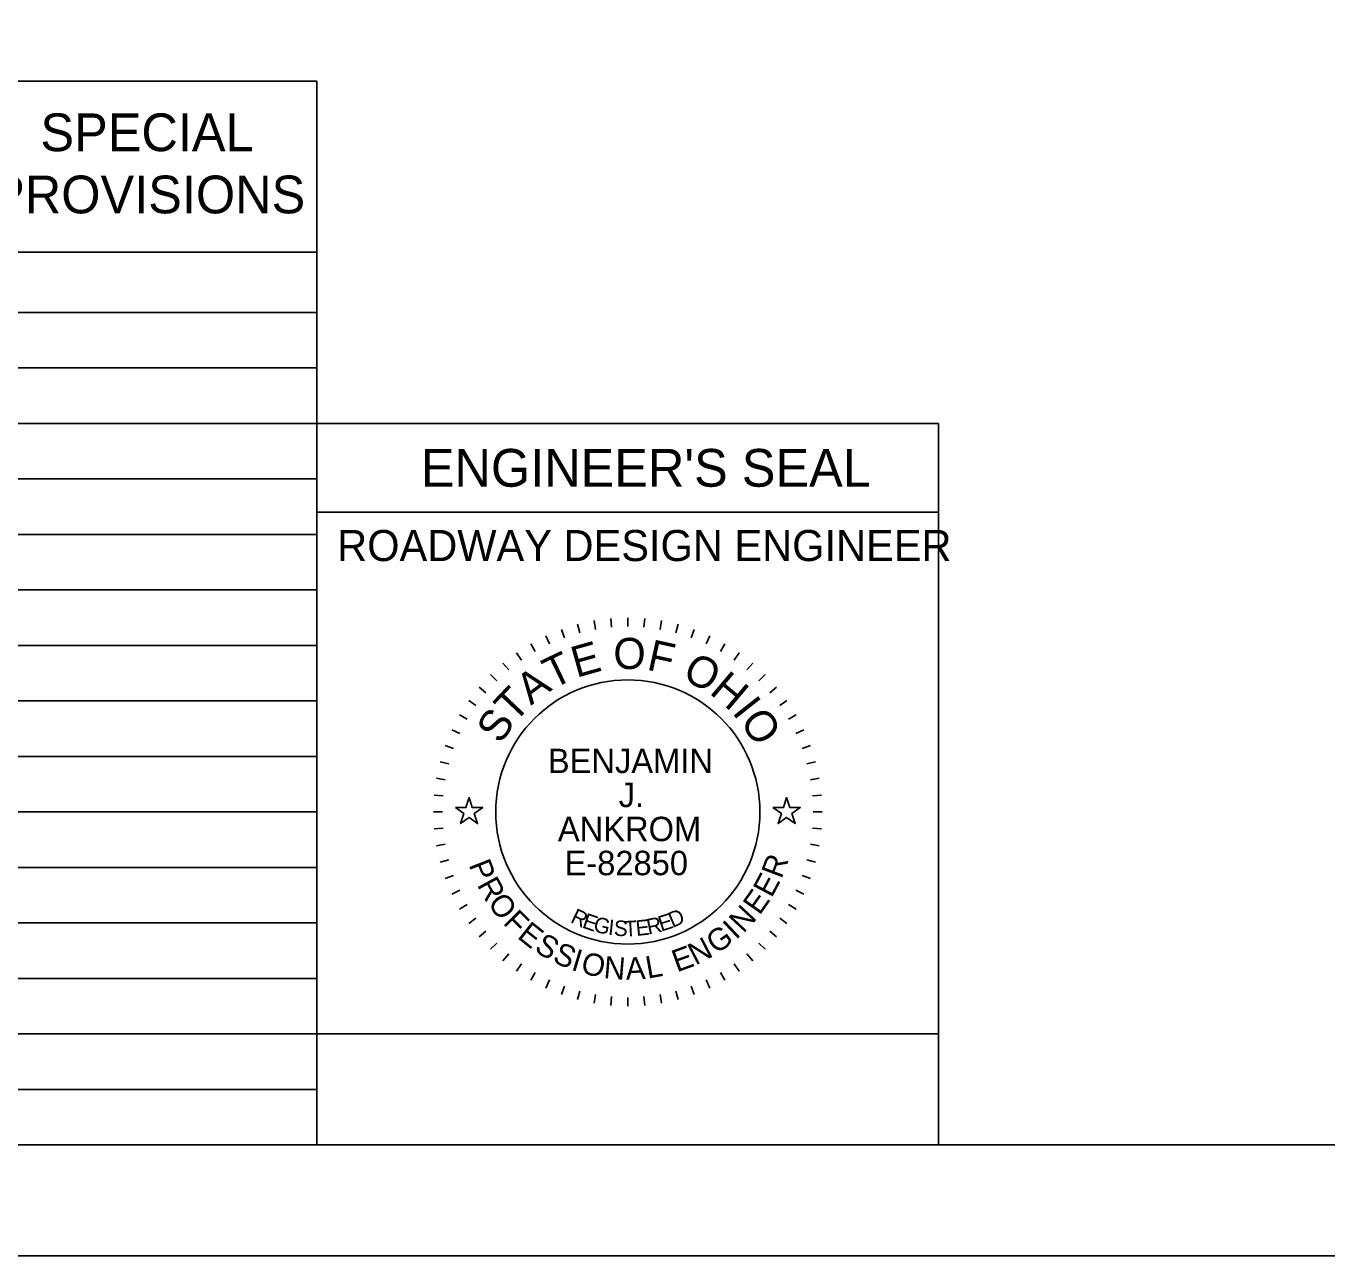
# Model space of a CAD drawing. Extents: x 0 to 34, y 0 to 22.
# Drawn here: x 22.29 to 28.15, y 0 to 5.54 of the extents above; entities that cross this region are included whole.
import ezdxf

# ---------------------------------------------------------------- set-up
doc = ezdxf.new("R2010")
doc.units = 0
for name, color, linetype in [('Default', 7, 'Continuous'), ('SH_Border', 7, 'Continuous'), ('SH_Cut_Line', 7, 'Continuous'), ('SH_Data', 7, 'Continuous'), ('SH_Text', 7, 'Continuous')]:
    doc.layers.add(name, color=color, linetype=linetype)

msp = doc.modelspace()

# ---------------------------------------------------------------- linework, layer by layer
at = {"layer": 'Default'}
for points in [[(24.2236, 2.02), (24.2705, 2.02), (24.285, 2.0645), (24.2995, 2.02), (24.3464, 2.02), (24.3085, 1.9924), (24.323, 1.9478), (24.285, 1.9754), (24.247, 1.9478), (24.2615, 1.9924)], [(25.6536, 2.02), (25.7005, 2.02), (25.715, 2.0645), (25.7295, 2.02), (25.7764, 2.02), (25.7385, 1.9924), (25.753, 1.9478), (25.715, 1.9754), (25.677, 1.9478), (25.6915, 1.9924)]]:
    msp.add_lwpolyline(points, close=True, dxfattribs=at)
at = {"layer": 'SH_Border'}
msp.add_lwpolyline([(1.5, 21.5), (33.5, 21.5), (33.5, 0.5), (1.5, 0.5)], close=True, dxfattribs=at)
at = {"layer": 'SH_Cut_Line'}
msp.add_lwpolyline([(0, 0), (34, 0), (34, 22), (0, 22)], close=True, dxfattribs=at)
at = {"layer": 'SH_Data'}
for p, q in [((10.15, 5.2917), (23.6, 5.2917)), ((23.6, 0.5), (23.6, 5.2917)), ((10.15, 4.5209), (23.6, 4.5209)), ((10.15, 4.25), (23.6, 4.25)), ((10.15, 4), (23.6, 4)), ((10.15, 3.75), (23.6, 3.75)), ((23.6, 0.5), (23.6, 3.75)), ((23.6, 3.75), (26.4, 3.75)), ((26.4, 3.75), (26.4, 0.5)), ((10.15, 3.5), (23.6, 3.5)), ((23.6, 3.35), (26.4, 3.35)), ((10.15, 3.25), (23.6, 3.25)), ((10.15, 3), (23.6, 3)), ((24.9237, 2.8717), (24.9272, 2.8318)), ((25, 2.875), (25, 2.835)), ((25.0763, 2.8717), (25.0728, 2.8318)), ((24.7007, 2.8222), (24.7144, 2.7846)), ((24.7735, 2.8452), (24.7839, 2.8065)), ((24.8481, 2.8617), (24.855, 2.8223)), ((25.1519, 2.8617), (25.145, 2.8223)), ((25.2265, 2.8452), (25.2161, 2.8065)), ((25.2993, 2.8222), (25.2856, 2.7846)), ((24.5625, 2.7578), (24.5825, 2.7231)), ((24.6302, 2.793), (24.6471, 2.7568)), ((25.3698, 2.793), (25.3529, 2.7568)), ((25.4375, 2.7578), (25.4175, 2.7231)), ((10.15, 2.75), (23.6, 2.75)), ((24.4981, 2.7168), (24.5211, 2.684)), ((25.5019, 2.7168), (25.4789, 2.684)), ((24.4376, 2.6703), (24.4633, 2.6396)), ((25.5624, 2.6703), (25.5367, 2.6396)), ((24.3813, 2.6187), (24.4096, 2.5904)), ((25.6187, 2.6187), (25.5904, 2.5904)), ((24.3297, 2.5624), (24.3604, 2.5367)), ((25.6703, 2.5624), (25.6396, 2.5367)), ((10.15, 2.5), (23.6, 2.5)), ((24.2832, 2.5019), (24.316, 2.4789)), ((25.7168, 2.5019), (25.684, 2.4789)), ((24.2422, 2.4375), (24.2769, 2.4175)), ((25.7578, 2.4375), (25.7231, 2.4175)), ((24.207, 2.3698), (24.2432, 2.3529)), ((25.793, 2.3698), (25.7568, 2.3529)), ((24.1778, 2.2993), (24.2154, 2.2856)), ((25.8222, 2.2993), (25.7846, 2.2856)), ((10.15, 2.25), (23.6, 2.25)), ((24.1548, 2.2265), (24.1935, 2.2161)), ((25.8452, 2.2265), (25.8065, 2.2161)), ((24.1383, 2.1519), (24.1777, 2.145)), ((25.8617, 2.1519), (25.8223, 2.145)), ((24.1283, 2.0763), (24.1682, 2.0728)), ((25.8717, 2.0763), (25.8318, 2.0728)), ((10.15, 2), (23.6, 2)), ((24.125, 2), (24.165, 2)), ((25.875, 2), (25.835, 2)), ((24.1283, 1.9237), (24.1682, 1.9272)), ((25.8717, 1.9237), (25.8318, 1.9272)), ((24.1383, 1.8481), (24.1777, 1.855)), ((25.8617, 1.8481), (25.8223, 1.855)), ((24.1548, 1.7735), (24.1935, 1.7839)), ((25.8452, 1.7735), (25.8065, 1.7839)), ((10.15, 1.75), (23.6, 1.75)), ((24.1778, 1.7007), (24.2154, 1.7144)), ((25.8222, 1.7007), (25.7846, 1.7144)), ((24.207, 1.6302), (24.2432, 1.6471)), ((25.793, 1.6302), (25.7568, 1.6471)), ((24.2422, 1.5625), (24.2769, 1.5825)), ((25.7578, 1.5625), (25.7231, 1.5825)), ((10.15, 1.5), (23.6, 1.5)), ((24.2832, 1.4981), (24.316, 1.5211)), ((25.7168, 1.4981), (25.684, 1.5211)), ((24.3297, 1.4376), (24.3604, 1.4633)), ((24.3813, 1.3813), (24.4096, 1.4096)), ((25.6187, 1.3813), (25.5904, 1.4096)), ((25.6703, 1.4376), (25.6396, 1.4633)), ((24.4376, 1.3297), (24.4633, 1.3604)), ((25.5624, 1.3297), (25.5367, 1.3604)), ((24.4981, 1.2832), (24.5211, 1.316)), ((25.5019, 1.2832), (25.4789, 1.316)), ((10.15, 1.25), (23.6, 1.25)), ((24.5625, 1.2422), (24.5825, 1.2769)), ((24.6302, 1.207), (24.6471, 1.2432)), ((25.3698, 1.207), (25.3529, 1.2432)), ((25.4375, 1.2422), (25.4175, 1.2769)), ((24.7007, 1.1778), (24.7144, 1.2154)), ((24.7735, 1.1548), (24.7839, 1.1935)), ((24.8481, 1.1383), (24.855, 1.1777)), ((25.1519, 1.1383), (25.145, 1.1777)), ((25.2265, 1.1548), (25.2161, 1.1935)), ((25.2993, 1.1778), (25.2856, 1.2154)), ((24.9237, 1.1283), (24.9272, 1.1682)), ((25, 1.125), (25, 1.165)), ((25.0763, 1.1283), (25.0728, 1.1682)), ((10.15, 1), (23.6, 1)), ((10.15, 0.75), (23.6, 0.75)), ((23.6, 0.5), (26.4, 0.5))]:
    msp.add_line(p, q, dxfattribs=at)
msp.add_lwpolyline([(23.6, 0.5), (23.6, 1), (26.4, 1), (26.4, 0.5)], close=True, dxfattribs=at)
msp.add_circle((25, 2), 0.595, dxfattribs=at)

# ---------------------------------------------------------------- texts
for s, height, p in [("ENGINEER'S SEAL", 0.17, (24.0676, 3.465)), ('ROADWAY DESIGN ENGINEER', 0.14, (23.691, 3.13)), ('BENJAMIN', 0.11, (24.6397, 2.1749)), ('J.', 0.11, (24.9587, 2.0216)), ('ANKROM', 0.11, (24.6849, 1.8684)), ('E-82850', 0.11, (24.7149, 1.7151))]:
    msp.add_text(s, height=height, dxfattribs=at).set_placement(p)
for s, height, rotation, p in [('E', 0.14, 15.75706, (24.7684, 2.6038)), ('O', 0.14, 359.78119, (24.9347, 2.6443)), ('F', 0.14, 347.43619, (25.0811, 2.6417)), ('T', 0.14, 25.71674, (24.6616, 2.5518)), ('O', 0.14, 332.25863, (25.2398, 2.6015)), ('A', 0.14, 36.47472, (24.5634, 2.4781)), ('H', 0.14, 319.91363, (25.3632, 2.5361)), ('T', 0.14, 46.4344, (24.4883, 2.3964)), ('I', 0.14, 308.36695, (25.4665, 2.4483)), ('S', 0.14, 57.19238, (24.4281, 2.3014)), ('O', 0.14, 303.14906, (25.5021, 2.4089)), ('P', 0.1, 291.49398, (24.2823, 1.7621)), ('R', 0.1, 69.23216, (25.6919, 1.6954)), ('R', 0.1, 298.73106, (24.319, 1.6717)), ('E', 0.1, 61.99508, (25.6476, 1.6098)), ('E', 0.1, 54.75801, (25.5933, 1.5314)), ('O', 0.1, 306.46664, (24.3655, 1.5883)), ('F', 0.1, 314.7068, (24.4343, 1.4983)), ('R', 0.07, 334.48695, (24.7375, 1.5051)), ('E', 0.07, 341.03996, (24.7906, 1.4801)), ('G', 0.07, 347.47515, (24.8414, 1.4618)), ('R', 0.07, 11.91844, (25.0925, 1.4474)), ('E', 0.07, 17.68363, (25.1498, 1.4602)), ('D', 0.07, 23.30524, (25.201, 1.477)), ('N', 0.1, 47.02243, (25.5202, 1.4508)), ('E', 0.1, 321.43929, (24.4978, 1.4348)), ('I', 0.07, 353.78581, (24.9091, 1.4468)), ('S', 0.07, 356.89262, (24.9358, 1.4429)), ('T', 0.07, 3.00609, (24.9857, 1.4387)), ('E', 0.07, 6.01169, (25.0389, 1.4412)), ('G', 0.1, 35.04687, (25.3981, 1.357)), ('I', 0.1, 43.28703, (25.4868, 1.4214)), ('S', 0.1, 328.67637, (24.5743, 1.3752)), ('S', 0.1, 335.91345, (24.6564, 1.3266)), ('N', 0.1, 27.31129, (25.3045, 1.3075)), ('I', 0.1, 343.15053, (24.7406, 1.2897)), ('O', 0.1, 346.88592, (24.7839, 1.2751)), ('N', 0.1, 355.12608, (24.8888, 1.2517)), ('L', 0.1, 10.09874, (25.0894, 1.249)), ('E', 0.1, 20.07421, (25.2212, 1.277)), ('A', 0.1, 2.86166, (24.9923, 1.2437))]:
    msp.add_text(s, height=height, rotation=rotation, dxfattribs=at).set_placement(p)
at = {"layer": 'SH_Text'}
for s, p in [('SPECIAL', (22.3542, 4.9763)), ('PROVISIONS', (22.1323, 4.6963))]:
    msp.add_text(s, height=0.17, dxfattribs=at).set_placement(p)

doc.saveas('drawing.dxf')
